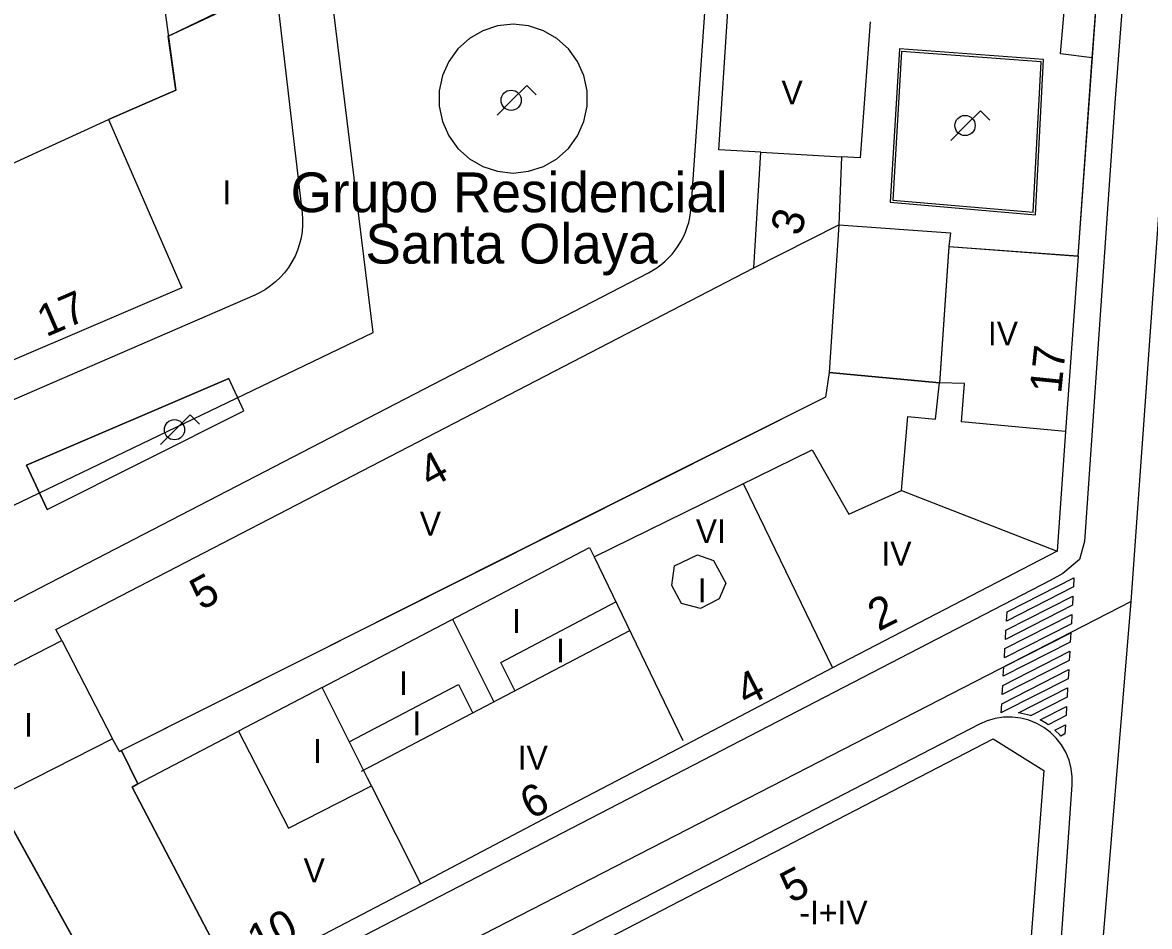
# Model space of a CAD drawing. Extents: x 282771 to 285132, y 4823109 to 4825496.
# Drawn here: x 282930.6 to 283001.5, y 4824226.7 to 4824283.6 of the extents above; entities that cross this region are included whole.
import ezdxf

# ---------------------------------------------------------------- set-up
doc = ezdxf.new("R2010")
doc.units = 0
for name, color, linetype in [('ACERA-BORDILLO', 7, 'Continuous'), ('ACERA-INTERIOR', 7, 'Continuous'), ('BORDILLO', 7, 'Continuous'), ('CALLE-EJE', 7, 'Continuous'), ('EDIFICIO', 7, 'Continuous'), ('FAROLA', 7, 'Continuous'), ('INTERIOR-EDIFICIO', 7, 'Continuous'), ('MEDIANERA', 7, 'Continuous'), ('NUM-PORTAL', 7, 'Continuous'), ('PASO-PEATONES', 7, 'Continuous'), ('TXT-ALTURA-EDIFICIO', 7, 'Continuous'), ('URBANIZACION-AREA', 7, 'Continuous'), ('URBANIZACION-TEXTO', 7, 'Continuous'), ('ZONA-VERDE', 7, 'Continuous')]:
    doc.layers.add(name, color=color, linetype=linetype)

msp = doc.modelspace()

# ---------------------------------------------------------------- linework, layer by layer
at = {"layer": 'ACERA-BORDILLO'}
for points in [[(283003.032, 4824331.195), (283000.619, 4824295.551), (282999.329, 4824278.551), (282997.419, 4824250.941), (282997.109, 4824249.822), (282996.059, 4824248.922), (282995.249, 4824248.492), (282944.455, 4824222.183)], [(282992.498, 4824180.941), (282993.369, 4824190.332), (282995.599, 4824220.562), (282996.649, 4824235.622), (282996.652, 4824236.135), (282996.587, 4824236.657), (282996.45, 4824237.176), (282996.243, 4824237.676), (282995.971, 4824238.143), (282995.641, 4824238.566), (282995.265, 4824238.934), (282994.855, 4824239.243), (282994.409, 4824239.496), (282993.922, 4824239.695), (282993.403, 4824239.83), (282992.865, 4824239.894), (282992.324, 4824239.886), (282991.794, 4824239.805), (282991.289, 4824239.658), (282990.819, 4824239.452), (282978.039, 4824232.832), (282891.09, 4824187.712), (282879.21, 4824181.652), (282849.03, 4824166.202)]]:
    msp.add_lwpolyline(points, dxfattribs=at)
at = {"layer": 'ACERA-INTERIOR'}
for points in [[(282891.09, 4824227.012), (282969.977, 4824267.864), (282970.509, 4824268.183), (282970.764, 4824268.37), (282971.009, 4824268.575), (282971.242, 4824268.798), (282971.462, 4824269.037), (282971.667, 4824269.29), (282971.855, 4824269.557), (282972.026, 4824269.836), (282972.177, 4824270.124), (282972.309, 4824270.421), (282972.421, 4824270.724), (282972.512, 4824271.03), (282972.583, 4824271.339), (282972.665, 4824271.954), (282974.179, 4824293.551)], [(282997.909, 4824281.401), (282995.909, 4824281.641), (282996.409, 4824287.451), (282998.349, 4824287.211)], [(282997.909, 4824281.401), (282998.349, 4824287.211)], [(282946.514, 4824286.032), (282948.184, 4824271.615), (282948.213, 4824271.24), (282948.214, 4824270.855), (282948.184, 4824270.463), (282948.122, 4824270.069), (282948.027, 4824269.675), (282947.9, 4824269.287), (282947.74, 4824268.908), (282947.549, 4824268.542), (282947.328, 4824268.193), (282947.08, 4824267.865), (282946.808, 4824267.56), (282946.515, 4824267.282), (282946.204, 4824267.03), (282945.88, 4824266.808), (282945.547, 4824266.616), (282945.207, 4824266.453), (282891.09, 4824242.982)], [(282946.514, 4824286.032), (282939.77, 4824282.761)], [(282960.49, 4824283.401), (282959.56, 4824283.101), (282958.71, 4824282.611), (282957.99, 4824281.961), (282957.41, 4824281.171), (282957.01, 4824280.271), (282956.81, 4824279.311), (282956.81, 4824278.341), (282957.01, 4824277.381), (282957.41, 4824276.481), (282957.99, 4824275.691), (282958.71, 4824275.041), (282959.56, 4824274.551), (282960.49, 4824274.251), (282961.469, 4824274.141), (282962.439, 4824274.251), (282963.369, 4824274.551), (282964.219, 4824275.041), (282964.939, 4824275.691), (282965.519, 4824276.481), (282965.919, 4824277.381), (282966.119, 4824278.341), (282966.119, 4824279.311), (282965.919, 4824280.271), (282965.519, 4824281.171), (282964.939, 4824281.961), (282964.219, 4824282.611), (282963.369, 4824283.101), (282962.439, 4824283.401), (282961.469, 4824283.511), (282960.49, 4824283.401)], [(282997.019, 4824268.911), (282997.909, 4824281.401)]]:
    msp.add_lwpolyline(points, dxfattribs=at)
at = {"layer": 'BORDILLO'}
msp.add_lwpolyline([(282985.189, 4824272.301), (282994.339, 4824271.511), (282994.839, 4824281.291), (282985.769, 4824281.951), (282985.189, 4824272.301)], dxfattribs=at)
at = {"layer": 'CALLE-EJE'}
for points in [[(283000.359, 4824247.161), (283003.809, 4824295.551), (283007.919, 4824341.461)], [(282853.391, 4824216.392), (282952.66, 4824264.101), (282948.79, 4824295.551), (282942.69, 4824333.861)], [(283000.359, 4824247.161), (282843.321, 4824166.432)], [(282994.379, 4824174.892), (283000.359, 4824247.161)]]:
    msp.add_lwpolyline(points, dxfattribs=at)
at = {"layer": 'EDIFICIO'}
for points in [[(282898.88, 4824321.471), (282912.62, 4824323.091), (282940.34, 4824326.381), (282943.34, 4824301.671), (282937.27, 4824300.901), (282938.01, 4824295.551), (282940.25, 4824279.361), (282936, 4824277.511), (282940.61, 4824266.921), (282891.09, 4824245.691), (282839.261, 4824223.472), (282829.681, 4824220.082), (282826.381, 4824230.322), (282817.731, 4824256.931), (282808.881, 4824283.891), (282805.061, 4824295.551), (282801.621, 4824306.061), (282803.871, 4824310.071), (282873.52, 4824318.471), (282891.09, 4824320.541), (282898.88, 4824321.471)], [(282910.47, 4824233.912), (282925.29, 4824241.602), (282925.77, 4824240.972), (282933.06, 4824244.712), (282932.68, 4824245.412), (282957.8, 4824258.421), (282976.609, 4824268.181), (282977.059, 4824275.451), (282974.399, 4824275.601), (282974.969, 4824284.321)], [(282983.939, 4824283.651), (282983.309, 4824275.091), (282982.119, 4824275.161), (282981.959, 4824270.881), (282988.989, 4824270.381), (282988.889, 4824269.511), (282997.019, 4824268.911), (282996.229, 4824257.871), (282995.689, 4824250.342), (282981.569, 4824242.982), (282974.889, 4824239.492), (282972.289, 4824238.132), (282964.129, 4824233.862), (282955.65, 4824229.402), (282943.9, 4824223.242), (282937.49, 4824235.472), (282937.84, 4824235.682), (282936.815, 4824237.789), (282936.7, 4824237.732), (282936.25, 4824238.512), (282928.9, 4824234.782)], [(282990.912, 4824182.427), (282974.229, 4824174.022), (282972.518, 4824173.161), (282957.228, 4824203.511), (282955.196, 4824207.543), (282957.875, 4824208.893), (282953.036, 4824218.498), (282959.61, 4824221.902), (282966.479, 4824225.472), (282973.599, 4824229.162), (282978.599, 4824231.752), (282980.129, 4824232.542), (282991.679, 4824238.532), (282994.849, 4824236.532), (282994.189, 4824227.742), (282993.559, 4824219.492), (282993.309, 4824215.712), (282992.989, 4824211.212), (282992.379, 4824202.892), (282991.829, 4824195.172), (282990.912, 4824182.427)], [(282929.282, 4824234.093), (282935.97, 4824222.042), (282937.307, 4824219.802), (282927.17, 4824214.512)]]:
    msp.add_lwpolyline(points, dxfattribs=at)
at = {"layer": 'FAROLA'}
for p, q in [((282962.319, 4824279.651), (282961.379, 4824278.721)), ((282962.909, 4824279.061), (282962.319, 4824279.651)), ((282961.379, 4824278.721), (282960.45, 4824277.781)), ((282990.879, 4824278.061), (282989.939, 4824277.131)), ((282991.469, 4824277.471), (282990.879, 4824278.061)), ((282989.939, 4824277.131), (282989.009, 4824276.191)), ((282941.135, 4824258.912), (282940.195, 4824257.982)), ((282941.725, 4824258.322), (282941.135, 4824258.912)), ((282940.195, 4824257.982), (282939.265, 4824257.042))]:
    msp.add_line(p, q, dxfattribs=at)
for centre in [(282961.339, 4824278.721), (282989.899, 4824277.131), (282940.155, 4824257.982)]:
    msp.add_circle(centre, 0.637, dxfattribs=at)
at = {"layer": 'INTERIOR-EDIFICIO'}
for points in [[(282891.09, 4824256.921), (282907.25, 4824264.331), (282936, 4824277.511)], [(282977.059, 4824275.451), (282982.119, 4824275.161)], [(282976.609, 4824268.181), (282981.959, 4824270.881)], [(282937.84, 4824235.682), (282944.185, 4824239.001), (282947.33, 4824232.892), (282952.55, 4824235.567), (282952.305, 4824236.054), (282950.912, 4824238.823), (282949.44, 4824241.75), (282957.95, 4824246.202), (282966.27, 4824250.568), (282966.557, 4824249.976), (282980.289, 4824256.711), (282982.599, 4824252.671), (282985.909, 4824254.161), (282986.309, 4824258.821), (282988.039, 4824258.641), (282988.299, 4824260.931), (282981.359, 4824261.591), (282981.119, 4824260.041), (282974.833, 4824256.884), (282965.077, 4824251.984), (282957.061, 4824247.958), (282948.477, 4824243.647), (282936.815, 4824237.789)], [(282974.069, 4824249.751), (282974.859, 4824248.322), (282974.439, 4824247.332), (282973.259, 4824246.732), (282972.069, 4824247.052), (282971.449, 4824248.172), (282971.619, 4824249.421), (282973.069, 4824250.111), (282974.069, 4824249.751)]]:
    msp.add_lwpolyline(points, dxfattribs=at)
at = {"layer": 'MEDIANERA'}
for points in [[(282981.959, 4824270.881), (282981.359, 4824261.591), (282988.299, 4824260.931)], [(282988.889, 4824269.511), (282988.299, 4824260.931)], [(282996.229, 4824257.871), (282989.669, 4824258.471), (282989.859, 4824260.901), (282988.299, 4824260.931)], [(282975.969, 4824254.551), (282981.569, 4824242.982)], [(282985.909, 4824254.161), (282995.689, 4824250.342)], [(282966.557, 4824249.976), (282972.149, 4824238.422)], [(282961.591, 4824241.529), (282960.684, 4824243.335), (282967.931, 4824247.137)], [(282957.644, 4824246.048), (282960.25, 4824240.856)], [(282951.933, 4824236.486), (282968.802, 4824245.336)], [(282933.06, 4824244.712), (282936.25, 4824238.512)], [(282949.44, 4824241.75), (282944.185, 4824239.001)], [(282951.157, 4824238.337), (282958.027, 4824241.942), (282958.91, 4824240.183)], [(282955.65, 4824229.402), (282952.55, 4824235.567)]]:
    msp.add_lwpolyline(points, dxfattribs=at)
at = {"layer": 'PASO-PEATONES'}
for points in [[(282992.543, 4824246.515), (282996.757, 4824248.661), (282996.724, 4824248.083), (282992.51, 4824245.937)], [(282996.657, 4824246.927), (282992.443, 4824244.781), (282992.477, 4824245.359), (282996.69, 4824247.505)], [(282996.59, 4824245.771), (282992.377, 4824243.624), (282992.41, 4824244.202), (282996.624, 4824246.349)], [(282996.524, 4824244.614), (282992.31, 4824242.468), (282992.343, 4824243.046), (282996.557, 4824245.193)], [(282996.457, 4824243.458), (282992.243, 4824241.312), (282992.276, 4824241.89), (282996.49, 4824244.036)], [(282992.207, 4824240.171), (282992.177, 4824240.167), (282992.21, 4824240.734), (282996.423, 4824242.88), (282996.39, 4824242.302), (282992.286, 4824240.212)], [(282993.458, 4824240.125), (282993.264, 4824240.149), (282996.357, 4824241.724), (282996.323, 4824241.146), (282994.027, 4824239.976), (282994.016, 4824239.981)], [(282995.02, 4824239.494), (282994.624, 4824239.719), (282996.29, 4824240.568), (282996.257, 4824239.989), (282995.127, 4824239.414)], [(282995.865, 4824238.766), (282995.554, 4824239.071), (282996.223, 4824239.411), (282996.19, 4824238.833), (282995.92, 4824238.696)]]:
    msp.add_lwpolyline(points, close=True, dxfattribs=at)
at = {"layer": 'URBANIZACION-AREA'}
for points in [[(282999.287, 4824300.681), (282997.007, 4824268.901), (282988.877, 4824269.501), (282988.287, 4824260.921), (282981.346, 4824261.581), (282981.119, 4824260.041), (282936.7, 4824237.732), (282936.815, 4824237.789), (282937.84, 4824235.682), (282937.49, 4824235.472), (282943.9, 4824223.242), (282937.307, 4824219.802), (282935.97, 4824222.042), (282933.449, 4824226.586), (282930.346, 4824232.176), (282929.282, 4824234.093), (282919.335, 4824228.66), (282847.713, 4824191.5)], [(282834.424, 4824230.948), (282877.455, 4824250.669), (282936, 4824277.511), (282940.25, 4824279.361), (282939.756, 4824282.751), (282944.605, 4824285.053)]]:
    msp.add_lwpolyline(points, dxfattribs=at)
at = {"layer": 'ZONA-VERDE'}
for p, q in [((282930.841, 4824255.755), (282943.569, 4824261.217)), ((282943.569, 4824261.217), (282930.841, 4824255.755)), ((282944.524, 4824259.165), (282943.569, 4824261.217)), ((282944.524, 4824259.165), (282943.569, 4824261.217)), ((282932.14, 4824252.963), (282944.524, 4824259.165)), ((282932.14, 4824252.963), (282944.524, 4824259.165)), ((282932.14, 4824252.963), (282930.841, 4824255.755)), ((282930.841, 4824255.755), (282932.14, 4824252.963))]:
    msp.add_line(p, q, dxfattribs=at)
msp.add_lwpolyline([(282994.197, 4824271.674), (282994.682, 4824281.152), (282985.91, 4824281.791), (282985.348, 4824272.438), (282994.197, 4824271.674)], dxfattribs=at)

# ---------------------------------------------------------------- texts
at = {"layer": 'NUM-PORTAL'}
for s, rotation, p in [('3', 74.63004, (282979.548, 4824270.114)), ('17', 23.33004, (282932.073, 4824263.794)), ('17', 84.04004, (282995.946, 4824260.217)), ('4', 28.51004, (282956.242, 4824254.267)), ('5', 28.51004, (282941.843, 4824246.582)), ('2', 27.08004, (282984.458, 4824245.265)), ('4', 27.08004, (282976.149, 4824240.529)), ('6', 27.08004, (282962.576, 4824233.412)), ('5', 27.57004, (282978.958, 4824228.132)), ('10', 27.08004, (282945.42, 4824224.779))]:
    msp.add_text(s, height=2, rotation=rotation, dxfattribs=at).set_placement(p)
at = {"layer": 'TXT-ALTURA-EDIFICIO'}
for s, p in [('V', (282978.35, 4824278.461)), ('I', (282943.18, 4824272.18)), ('IV', (282991.34, 4824263.291)), ('V', (282955.591, 4824251.321)), ('VI', (282972.96, 4824250.851)), ('IV', (282984.64, 4824249.431)), ('I', (282973.078, 4824247.122)), ('I', (282961.4, 4824245.195)), ('I', (282964.171, 4824243.328)), ('I', (282954.291, 4824241.279)), ('I', (282930.699, 4824238.652)), ('I', (282955.134, 4824238.749)), ('I', (282948.869, 4824237.002)), ('IV', (282961.752, 4824236.583)), ('V', (282948.281, 4824229.492)), ('-I+IV', (282979.479, 4824226.834))]:
    msp.add_text(s, height=1.5, rotation=0.00004, dxfattribs=at).set_placement(p)
at = {"layer": 'URBANIZACION-TEXTO'}
for s, p in [('Grupo Residencial ', (282947.463, 4824271.676)), ('Santa Olaya', (282952.17, 4824268.443))]:
    msp.add_text(s, height=2.5, dxfattribs=at).set_placement(p)

doc.saveas('drawing.dxf')
